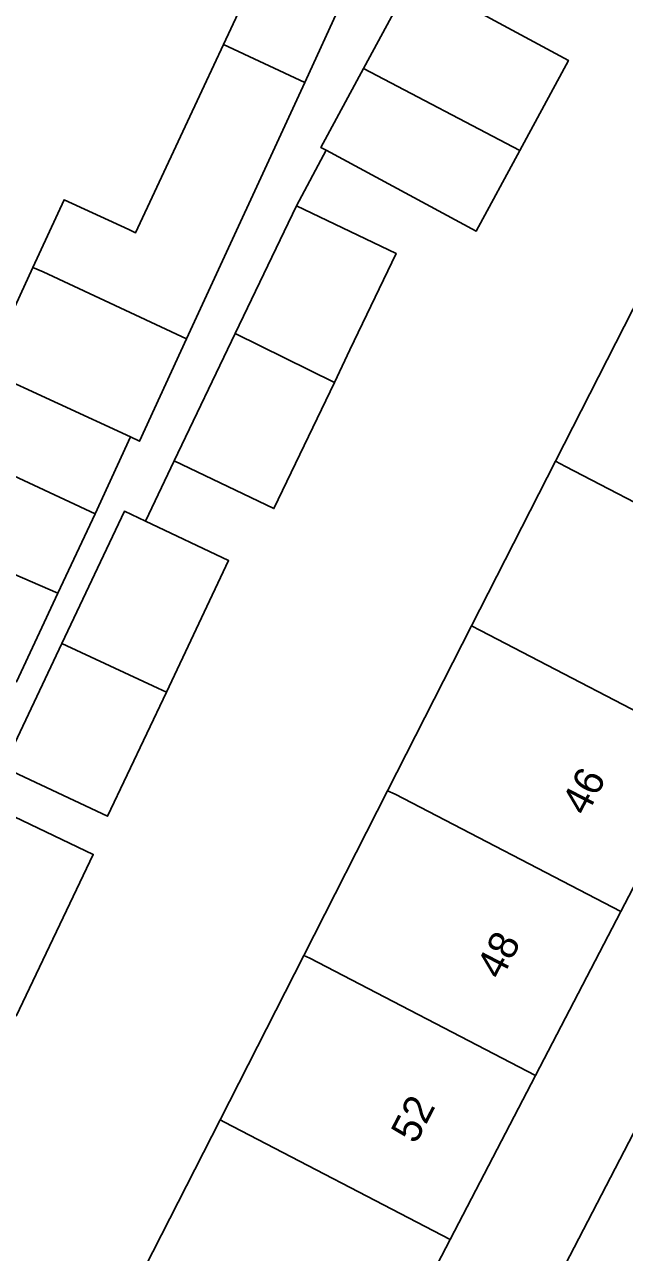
# Model space of a CAD drawing. Extents: x 160349 to 161355, y 381727 to 382854.
# Drawn here: x 160747.8 to 160768.15, y 382012.59 to 382054.29 of the extents above; entities that cross this region are included whole.
import ezdxf

# ---------------------------------------------------------------- set-up
doc = ezdxf.new("R2010")
doc.units = 0
for name, color, linetype in [('IMGEO_Erf', 7, 'Continuous'), ('IMGEO_Pand', 7, 'Continuous'), ('IMGEO_Pand_nummerreeks', 7, 'Continuous'), ('IMGEO_Voetpad_open', 7, 'Continuous')]:
    doc.layers.add(name, color=color, linetype=linetype)

msp = doc.modelspace()

# ---------------------------------------------------------------- linework, layer by layer
at = {"layer": 'IMGEO_Erf'}
for points in [[(160733.5, 381991.897), (160750, 381983.553), (160751.631, 381984.178), (160759.835, 382000), (160785.858, 382050.188), (160815.372, 382106.589)], [(160746.724, 382039.295), (160750.188, 382037.677), (160751.39, 382040.287), (160746.474, 382042.551), (160748.082, 382046.045), (160749.14, 382048.342), (160751.337, 382047.33), (160751.564, 382047.225), (160753.891, 382052.208), (160754.549, 382053.617), (160755.794, 382056.283)], [(160760.985, 382055.925), (160766.254, 382053.077), (160764.599, 382050.016), (160763.119, 382047.276), (160758.037, 382050.022), (160757.021, 382048.141), (160760.406, 382046.521), (160758.837, 382043.243), (160758.311, 382042.143), (160756.258, 382037.853), (160752.873, 382039.473), (160751.903, 382037.423), (160754.722, 382036.089), (160752.611, 382031.626), (160750.614, 382027.405), (160747.22, 382029.011)], [(160745.9, 382000.319), (160748.744, 382005.91), (160751.588, 382011.501), (160754.434, 382017.095), (160757.276, 382022.682), (160760.117, 382028.266), (160762.969, 382033.873), (160765.817, 382039.47), (160768.729, 382045.195), (160772.349, 382043.313), (160776.786, 382041.007), (160773.819, 382035.302), (160770.925, 382029.735), (160768.031, 382024.169), (160765.136, 382018.602), (160762.242, 382013.036), (160759.347, 382007.469), (160756.453, 382001.903), (160755.464, 382000), (160753.559, 381996.337), (160749.492, 381988.516), (160749.315, 381988.608), (160749.463, 381988.892), (160742.16, 381992.689)], [(160746.637, 382027.778), (160750.129, 382026.113), (160747.511, 382020.622)]]:
    msp.add_lwpolyline(points, dxfattribs=at)
at = {"layer": 'IMGEO_Pand'}
for points in [[(160758.545, 382055.017), (160755.794, 382056.283), (160754.549, 382053.617), (160757.306, 382052.327)], [(160764.599, 382050.016), (160766.254, 382053.077), (160760.985, 382055.925), (160759.299, 382052.804)], [(160757.306, 382052.327), (160754.549, 382053.617), (160753.891, 382052.208), (160751.564, 382047.225), (160751.337, 382047.33), (160749.14, 382048.342), (160748.082, 382046.045), (160748.428, 382045.9), (160753.297, 382043.617)], [(160759.299, 382052.804), (160757.85, 382050.123), (160758.037, 382050.022), (160763.119, 382047.276), (160764.599, 382050.016)], [(160758.311, 382042.143), (160758.837, 382043.243), (160760.406, 382046.521), (160757.021, 382048.141), (160754.946, 382043.803)], [(160753.297, 382043.617), (160748.428, 382045.9), (160748.082, 382046.045), (160746.474, 382042.551), (160751.39, 382040.287), (160751.699, 382040.145)], [(160765.817, 382039.47), (160766.159, 382039.285), (160773.819, 382035.302), (160776.786, 382041.007), (160772.349, 382043.313), (160768.729, 382045.195)], [(160758.311, 382042.143), (160754.946, 382043.803), (160752.873, 382039.473), (160756.258, 382037.853)], [(160770.925, 382029.735), (160773.819, 382035.302), (160766.159, 382039.285), (160765.817, 382039.47), (160762.969, 382033.873), (160763.265, 382033.718)], [(160750.188, 382037.677), (160746.724, 382039.295), (160745.717, 382037.137), (160745.837, 382036.887), (160746.181, 382036.174), (160748.929, 382034.981)], [(160754.722, 382036.089), (160751.903, 382037.423), (160751.184, 382037.763), (160749.062, 382033.277), (160752.317, 382031.758), (160752.611, 382031.626)], [(160748.929, 382034.981), (160746.181, 382036.174), (160745.837, 382036.887), (160744.257, 382033.503), (160747.525, 382031.976)], [(160770.925, 382029.735), (160763.265, 382033.718), (160762.969, 382033.873), (160760.117, 382028.266), (160760.371, 382028.152), (160768.031, 382024.169)], [(160752.611, 382031.626), (160752.317, 382031.758), (160749.062, 382033.277), (160747.076, 382029.079), (160747.22, 382029.011), (160750.614, 382027.405)], [(160765.136, 382018.602), (160768.031, 382024.169), (160760.371, 382028.152), (160760.117, 382028.266), (160757.276, 382022.682), (160757.476, 382022.585)], [(160747.511, 382020.622), (160750.129, 382026.113), (160746.637, 382027.778), (160744.011, 382022.269), (160747.195, 382020.783)], [(160765.136, 382018.602), (160757.476, 382022.585), (160757.276, 382022.682), (160754.434, 382017.095), (160754.582, 382017.019), (160762.242, 382013.036)], [(160759.347, 382007.469), (160762.242, 382013.036), (160754.582, 382017.019), (160754.434, 382017.095), (160751.588, 382011.501), (160751.687, 382011.452)]]:
    msp.add_lwpolyline(points, close=True, dxfattribs=at)
at = {"layer": 'IMGEO_Voetpad_open'}
for points in [[(160830.101, 382132.01), (160817.137, 382109.957), (160817.107, 382109.905), (160815.372, 382106.589), (160785.858, 382050.188), (160759.835, 382000), (160751.631, 381984.178), (160750, 381983.553), (160754.728, 381981.086)], [(160747.076, 382029.079), (160749.062, 382033.277), (160751.184, 382037.763), (160751.903, 382037.423), (160752.873, 382039.473), (160754.946, 382043.803), (160757.021, 382048.141), (160758.037, 382050.022), (160757.85, 382050.123), (160759.299, 382052.804), (160760.985, 382055.925)], [(160758.545, 382055.017), (160757.306, 382052.327), (160753.297, 382043.617), (160751.699, 382040.145), (160751.39, 382040.287), (160750.188, 382037.677), (160748.929, 382034.981), (160747.525, 382031.976)]]:
    msp.add_lwpolyline(points, dxfattribs=at)

# ---------------------------------------------------------------- texts
at = {"layer": 'IMGEO_Pand_nummerreeks'}
for s, rotation, p in [('46', 62.5256, (160766.861, 382027.381)), ('48', 62.5256, (160763.968, 382021.817)), ('52', 62.5274, (160761.071, 382016.246))]:
    msp.add_text(s, height=1, rotation=rotation, dxfattribs=at).set_placement(p)

doc.saveas('drawing.dxf')
